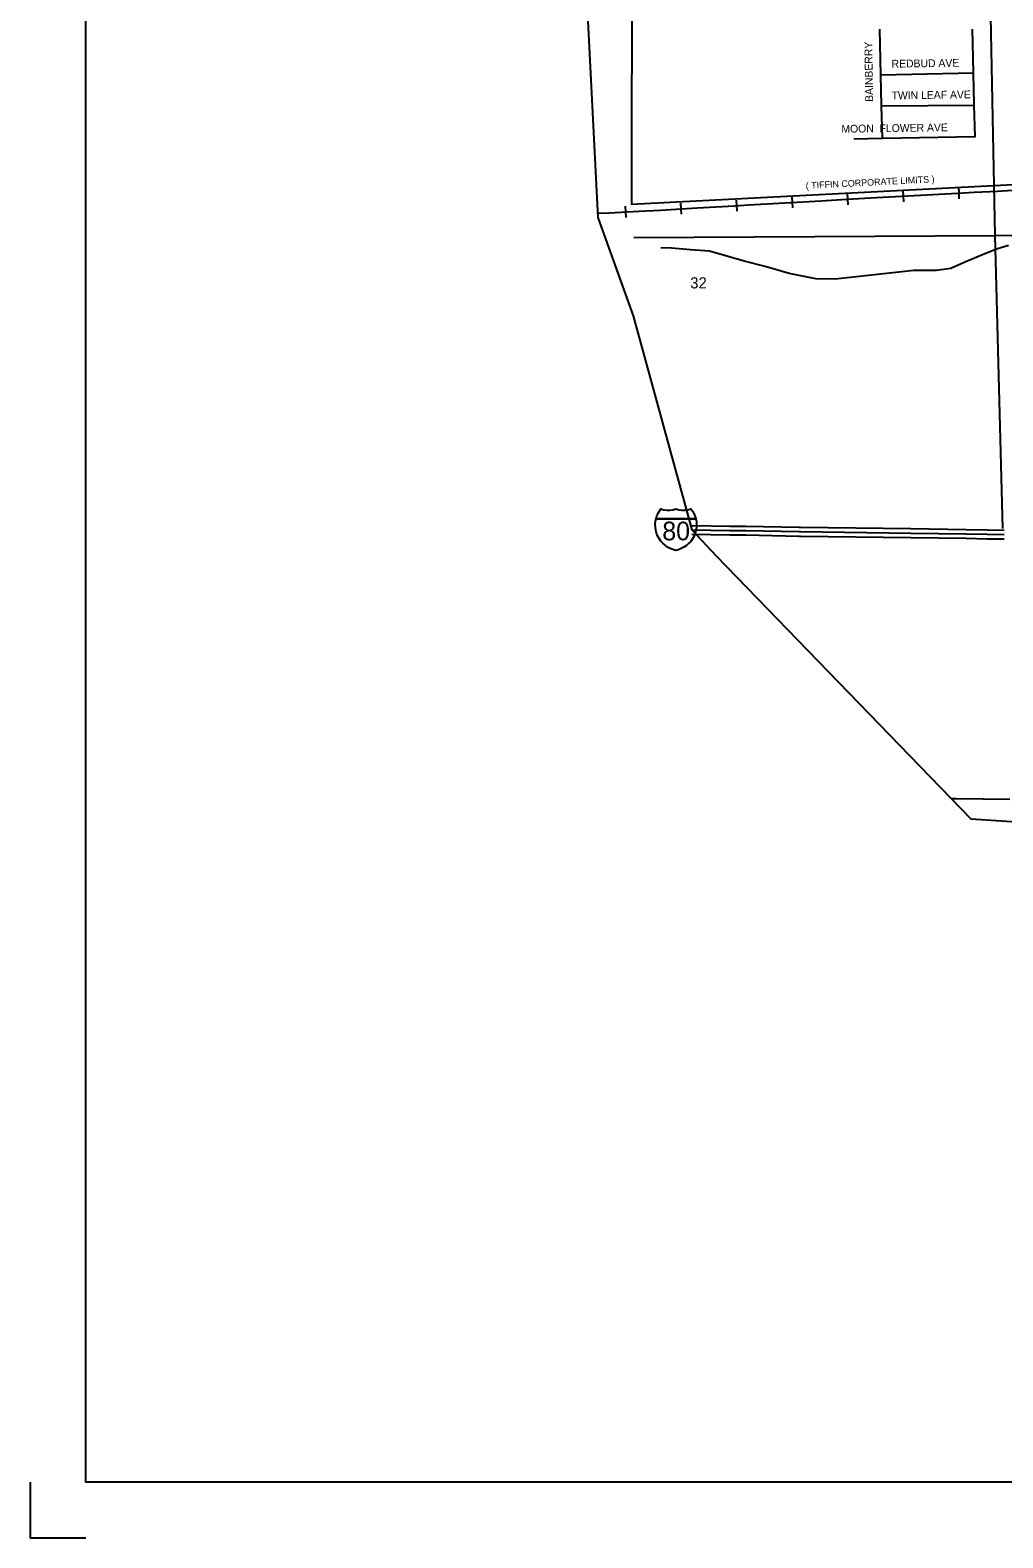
# Model space of a CAD drawing. Extents: x 281.94 to 289.14, y 116.09 to 120.89.
# Drawn here: x 281.938 to 283.686, y 116.087 to 118.797 of the extents above; entities that cross this region are included whole.
import ezdxf

# ---------------------------------------------------------------- set-up
doc = ezdxf.new("R2010")
doc.units = 0
for name, color, linetype in [('tdCiCityStreetCL', 7, 'Continuous'), ('tdCiCityStreetTxt', 7, 'Continuous'), ('tdCiCorpBndry', 7, 'Continuous'), ('tdCiCorpBndryPart', 7, 'Continuous'), ('tdCiCorpBndryTxt', 7, 'Continuous'), ('tdCiHydroRiver', 7, 'Continuous'), ('tdCiInt', 7, 'Continuous'), ('tdCiIntCL', 7, 'Continuous'), ('tdCiMapFrame', 7, 'Continuous'), ('tdCiMapPltShpe', 7, 'Continuous'), ('tdCiRRCL', 7, 'Continuous'), ('tdCiSecCL', 7, 'Continuous'), ('tdCiSectLine', 7, 'Continuous'), ('tdCiSectNmbr', 7, 'Continuous'), ('tdCiShieldInt', 7, 'Continuous')]:
    doc.layers.add(name, color=color, linetype=linetype)

msp = doc.modelspace()

# ---------------------------------------------------------------- linework, layer by layer
at = {"layer": 'tdCiCityStreetCL'}
for points in [[(283.4672, 118.7162), (283.4651, 118.7987)], [(283.6336, 118.7199), (283.6317, 118.7987)], [(283.4672, 118.7162), (283.6336, 118.7199)], [(283.4686, 118.6607), (283.4672, 118.7162)], [(283.635, 118.662), (283.6336, 118.7199)], [(283.4686, 118.6607), (283.635, 118.662)], [(283.4701, 118.6028), (283.4686, 118.6607)], [(283.4701, 118.6028), (283.6364, 118.6056), (283.635, 118.662)], [(283.4183, 118.6016), (283.4701, 118.6028)]]:
    msp.add_lwpolyline(points, dxfattribs=at)
at = {"layer": 'tdCiCorpBndry'}
msp.add_lwpolyline([(283.0197, 118.9514), (283.019, 118.4842), (284.0309, 118.536)], dxfattribs=at)
at = {"layer": 'tdCiCorpBndryPart'}
msp.add_lwpolyline([(283.0197, 118.9514), (283.019, 118.4842), (284.0309, 118.536), (284.0322, 118.4252), (284.1757, 118.4265)], dxfattribs=at)
at = {"layer": 'tdCiHydroRiver'}
msp.add_lwpolyline([(283.6967, 118.41), (283.6752, 118.4033), (283.65, 118.3929), (283.6167, 118.3789), (283.593, 118.3685), (283.5671, 118.3648), (283.5264, 118.3648), (283.385, 118.3493), (283.3502, 118.35), (283.3021, 118.3596), (283.2592, 118.3722), (283.2214, 118.3818), (283.1592, 118.3996), (283.1252, 118.4018), (283.0911, 118.4048), (283.0719, 118.4054)], dxfattribs=at)
at = {"layer": 'tdCiInt'}
for points in [[(283.1274, 117.8907), (283.1955, 117.8895), (283.2245, 117.8894), (283.3195, 117.8873), (283.3229, 117.8874), (283.5211, 117.8848), (283.6205, 117.8835), (283.6581, 117.8826), (283.6891, 117.8823)], [(283.1277, 117.9067), (283.1957, 117.9055), (283.2247, 117.9054), (283.3195, 117.9034), (283.3228, 117.9034), (283.5213, 117.9008), (283.6208, 117.8995), (283.6583, 117.8986), (283.6891, 117.8983)]]:
    msp.add_lwpolyline(points, dxfattribs=at)
at = {"layer": 'tdCiIntCL'}
msp.add_lwpolyline([(283.1275, 117.8987), (283.1956, 117.8975), (283.2246, 117.8974), (283.3195, 117.8954), (283.3228, 117.8954), (283.5212, 117.8928), (283.6206, 117.8915), (283.6582, 117.8906), (283.6891, 117.8903)], dxfattribs=at)
at = {"layer": 'tdCiMapFrame'}
for points in [[(289.038, 120.7868), (289.038, 116.1868), (282.038, 116.1868), (282.038, 120.7868), (289.038, 120.7868)], [(281.938, 116.1868), (281.938, 116.0868), (282.038, 116.0868)]]:
    msp.add_lwpolyline(points, dxfattribs=at)
at = {"layer": 'tdCiMapPltShpe'}
for p, q in [((282.9583, 118.4602), (283.0222, 118.2832)), ((283.1709, 117.8521), (283.629, 117.3793)), ((283.629, 117.3793), (285.715, 117.2447))]:
    msp.add_line(p, q, dxfattribs=at)
for points in [[(283.1548, 119.4871), (282.9263, 119.0965), (282.9583, 118.4602)], [(283.0222, 118.2832), (283.1275, 117.8987), (283.1709, 117.8521)]]:
    msp.add_lwpolyline(points, dxfattribs=at)
at = {"layer": 'tdCiRRCL'}
for points in [[(282.9579, 118.4676), (282.9791, 118.4685), (283.0325, 118.4716), (283.0709, 118.4733), (283.1372, 118.4776), (283.2043, 118.4812), (283.2291, 118.4829), (283.2945, 118.4865), (283.3599, 118.4902), (283.406, 118.493), (283.4594, 118.4958), (283.5385, 118.5001), (283.6056, 118.5037), (283.6348, 118.5053), (283.6768, 118.5076), (283.7219, 118.5104)], [(282.9579, 118.4676), (282.9791, 118.4685), (283.0325, 118.4716), (283.0709, 118.4733), (283.1372, 118.4776), (283.2043, 118.4812), (283.2291, 118.4829), (283.2945, 118.4865), (283.3599, 118.4902), (283.406, 118.493), (283.4594, 118.4958), (283.5385, 118.5001), (283.6056, 118.5037), (283.6348, 118.5053), (283.6768, 118.5076), (283.7219, 118.5104)], [(283.6082, 118.4938), (283.6077, 118.5038), (283.6071, 118.5138)], [(283.1091, 118.4658), (283.1084, 118.4758), (283.1078, 118.4858)], [(283.209, 118.4715), (283.2083, 118.4815), (283.2076, 118.4915)], [(283.3087, 118.4772), (283.3081, 118.4872), (283.3075, 118.4972)], [(283.4085, 118.4831), (283.4079, 118.4931), (283.4074, 118.5031)], [(283.5083, 118.4885), (283.5078, 118.4985), (283.5073, 118.5084)], [(283.0092, 118.4602), (283.0086, 118.4702), (283.008, 118.4802)]]:
    msp.add_lwpolyline(points, dxfattribs=at)
at = {"layer": 'tdCiSecCL'}
msp.add_lwpolyline([(283.594, 117.4155), (283.6033, 117.4156), (283.6993, 117.4146)], dxfattribs=at)
at = {"layer": 'tdCiSectLine'}
for points in [[(283.6863, 117.9011), (283.6724, 118.4278), (283.6641, 118.8524)], [(283.0233, 118.4242), (283.6724, 118.4278), (284.0307, 118.4288)]]:
    msp.add_lwpolyline(points, dxfattribs=at)
at = {"layer": 'tdCiShieldInt'}
msp.add_line((283.063, 117.9187), (283.1345, 117.9187), dxfattribs=at)
for points in [[(283.085, 117.9341), (283.0877, 117.9341), (283.0931, 117.9347), (283.0988, 117.9361), (283.104, 117.9348), (283.1094, 117.9341), (283.1148, 117.9341), (283.1202, 117.9347), (283.1259, 117.9361), (283.129, 117.9316), (283.1316, 117.9268), (283.1336, 117.9218), (283.1345, 117.9187), (283.1355, 117.9134), (283.1359, 117.908), (283.1357, 117.9026), (283.1348, 117.8972), (283.1333, 117.892), (283.1313, 117.887), (283.1286, 117.8823), (283.1254, 117.8779), (283.1217, 117.8739), (283.1176, 117.8703), (283.1131, 117.8673), (283.1083, 117.8648), (283.1032, 117.8629), (283.0988, 117.8618), (283.0935, 117.8632), (283.0885, 117.8651), (283.0837, 117.8677), (283.0793, 117.8708), (283.0752, 117.8744), (283.0716, 117.8785), (283.0685, 117.8829), (283.0659, 117.8877), (283.0639, 117.8928), (283.0625, 117.898), (283.0618, 117.9034), (283.0616, 117.9088), (283.0621, 117.9142), (283.063, 117.9187), (283.0647, 117.9239), (283.0669, 117.9288), (283.0697, 117.9335), (283.0716, 117.9361), (283.0769, 117.9348), (283.0823, 117.9341)], [(283.0988, 117.8618), (283.0935, 117.8632), (283.0885, 117.8651), (283.0837, 117.8677), (283.0793, 117.8708), (283.0752, 117.8744), (283.0716, 117.8785), (283.0685, 117.8829), (283.0659, 117.8877), (283.0639, 117.8928), (283.0625, 117.898), (283.0618, 117.9034), (283.0616, 117.9088), (283.0621, 117.9142), (283.063, 117.9187), (283.1345, 117.9187), (283.1355, 117.9134), (283.1359, 117.908), (283.1357, 117.9026), (283.1348, 117.8972), (283.1333, 117.892), (283.1313, 117.887), (283.1286, 117.8823), (283.1254, 117.8779), (283.1217, 117.8739), (283.1176, 117.8703), (283.1131, 117.8673), (283.1083, 117.8648), (283.1032, 117.8629)], [(283.063, 117.9187), (283.0647, 117.9239), (283.0669, 117.9288), (283.0697, 117.9335), (283.0716, 117.9361), (283.0769, 117.9348), (283.0823, 117.9341), (283.0877, 117.9341), (283.0931, 117.9347), (283.0988, 117.9361), (283.104, 117.9348), (283.1094, 117.9341), (283.1148, 117.9341), (283.1202, 117.9347), (283.1259, 117.9361), (283.129, 117.9316), (283.1316, 117.9268), (283.1336, 117.9218), (283.1345, 117.9187)]]:
    msp.add_lwpolyline(points, close=True, dxfattribs=at)

# ---------------------------------------------------------------- texts
at = {"layer": 'tdCiCityStreetTxt'}
for s, rotation, p in [('BAINBERRY', 90.8064, (283.4532, 118.6679)), ('REDBUD AVE', 0.8064, (283.4865, 118.7294)), ('TWIN LEAF AVE', 0.8064, (283.4865, 118.6724)), ('MOON  FLOWER AVE', 0.8064, (283.3963, 118.6124))]:
    msp.add_text(s, height=0.014, rotation=rotation, dxfattribs=at).set_placement(p)
at = {"layer": 'tdCiCorpBndryTxt'}
msp.add_text('( TIFFIN CORPORATE LIMITS )', height=0.012, rotation=2.976, dxfattribs=at).set_placement((283.3324, 118.5113))
at = {"layer": 'tdCiSectNmbr'}
msp.add_text('32', height=0.02, rotation=359.8767, dxfattribs=at).set_placement((283.1245, 118.3326))
at = {"layer": 'tdCiShieldInt'}
msp.add_text('80', height=0.03348, dxfattribs=at).set_placement((283.0743, 117.8798))

doc.saveas('drawing.dxf')
